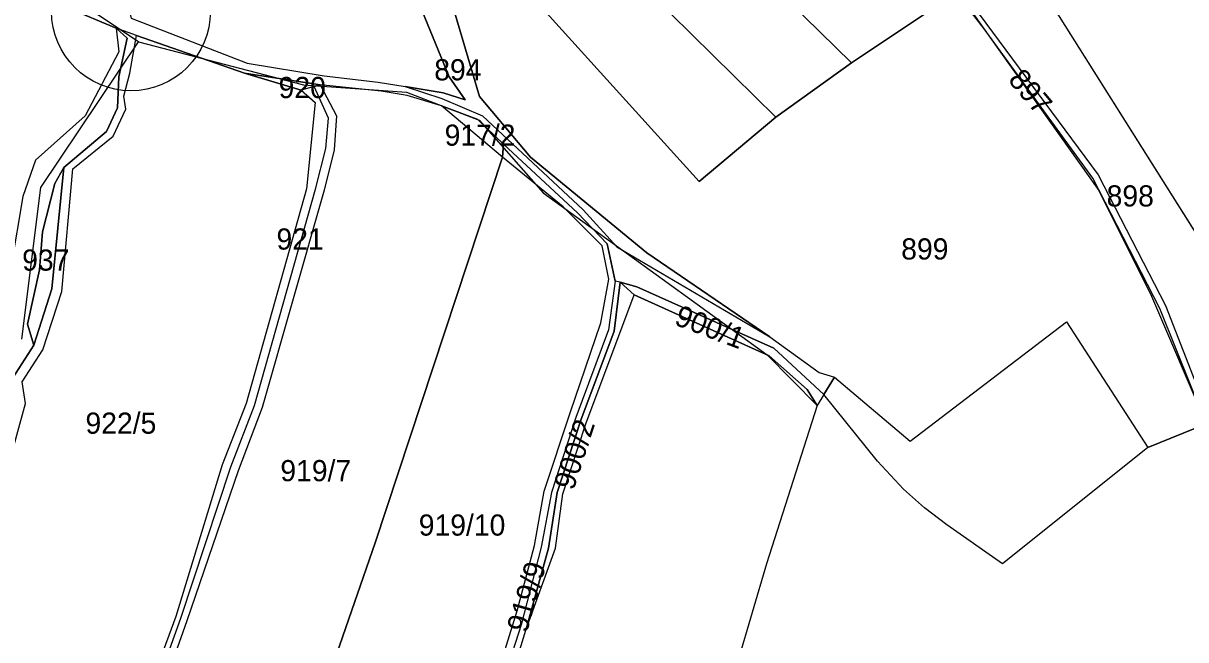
# Model space of a CAD drawing. Extents: x -623250 to -619626, y -1079612 to -1075424.
# Drawn here: x -621038 to -620489, y -1077899 to -1077608 of the extents above; entities that cross this region are included whole.
import ezdxf

# ---------------------------------------------------------------- set-up
doc = ezdxf.new("R2010")
doc.units = 0
for name, color, linetype in [('Bodové pole k revizi', 7, 'Continuous'), ('Cestní síť', 7, 'Continuous'), ('Hranice převzatá (KoPÚ Hrušová)', 7, 'Continuous'), ('Katastrální hranice', 7, 'Continuous'), ('Parcela nároku', 7, 'Continuous'), ('Parcelní číslo', 7, 'Continuous'), ('Vodní toky', 7, 'Continuous')]:
    doc.layers.add(name, color=color, linetype=linetype)

msp = doc.modelspace()

# ---------------------------------------------------------------- linework, layer by layer
at = {"layer": 'Bodové pole k revizi'}
msp.add_circle((-620987.23, -1077602.53), 37.5, dxfattribs=at)
at = {"layer": 'Cestní síť'}
for p, q in [((-620983.73, -1077616.96), (-621006.18, -1077601.9)), ((-621029.87, -1077685.72), (-620983.73, -1077616.96)), ((-620983.73, -1077616.96), (-620905.72, -1077637.25)), ((-620905.72, -1077637.25), (-620857.11, -1077640.69)), ((-620857.11, -1077640.69), (-620822.79, -1077653.85)), ((-620822.79, -1077653.85), (-620792.48, -1077688.19)), ((-621038.71, -1077757.43), (-621029.87, -1077685.72)), ((-620792.48, -1077688.19), (-620736.42, -1077728.82)), ((-620736.42, -1077728.82), (-620686.84, -1077764.76)), ((-620686.84, -1077764.76), (-620663.17, -1077788.68))]:
    msp.add_line(p, q, dxfattribs=at)
at = {"layer": 'Hranice převzatá (KoPÚ Hrušová)'}
msp.add_lwpolyline([(-620479.44, -1077797.32), (-620507, -1077808.5), (-620575.7, -1077863.52), (-620601.95, -1077845.15), (-620612.48, -1077837.08), (-620622.34, -1077828.19), (-620634.73, -1077815.07), (-620659.99, -1077783.48), (-620663.17, -1077788.68), (-620687.13, -1077863.5), (-620700.69, -1077909.5)], dxfattribs=at)
at = {"layer": 'Katastrální hranice'}
for p, q in [((-620453.81, -1077755.63), (-620553.25, -1077597.63)), ((-620619.25, -1077805.5), (-620545.44, -1077749.25)), ((-620545.44, -1077749.25), (-620507, -1077808.5)), ((-620659.99, -1077783.48), (-620654.94, -1077775.38)), ((-620654.94, -1077775.38), (-620619.25, -1077805.5))]:
    msp.add_line(p, q, dxfattribs=at)
at = {"layer": 'Parcela nároku'}
for points in [[(-620611.54, -1077603.19), (-620619.14, -1077595.91), (-620760.97, -1077460.03), (-620813.41, -1077411.33), (-620821.08, -1077412.33), (-620817.96, -1077433.72), (-620827.88, -1077444.11), (-620829.07, -1077450.57), (-620787.71, -1077488.88), (-620646.97, -1077626.81)], [(-620787.71, -1077488.88), (-620829.07, -1077450.57), (-620830.13, -1077456.35), (-620841.72, -1077495.6), (-620762.03, -1077574.2), (-620682.61, -1077652.52), (-620646.97, -1077626.81)], [(-620762.03, -1077574.2), (-620841.72, -1077495.6), (-620850.82, -1077526.41), (-620851.45, -1077542.42), (-620800.08, -1077592.94), (-620718.81, -1077682.81), (-620682.61, -1077652.52)], [(-620852.4, -1077595.58), (-620858.57, -1077544.04), (-620878.3, -1077553.15), (-620975.69, -1077586.93), (-620985.33, -1077593.45), (-620988.73, -1077599.5), (-620987.2, -1077605.73), (-620932.29, -1077627.05), (-620895.94, -1077632.9), (-620870.4, -1077635.97), (-620857.77, -1077638.01), (-620839.72, -1077640.92), (-620829.32, -1077644.28), (-620836.97, -1077633.47)], [(-620844.37, -1077593.81), (-620845.11, -1077577.39), (-620851.45, -1077542.42), (-620858.57, -1077544.04), (-620852.4, -1077595.58), (-620836.97, -1077633.47), (-620829.32, -1077644.28), (-620839.72, -1077640.92), (-620857.77, -1077638.01), (-620840.42, -1077643.71), (-620821.25, -1077651.89), (-620773.73, -1077696.26), (-620757.71, -1077713.72), (-620685.44, -1077756.32), (-620743.55, -1077716.58), (-620798.58, -1077671.35), (-620822.67, -1077642.69), (-620834.66, -1077602.26)], [(-620718.81, -1077682.81), (-620800.08, -1077592.94), (-620851.45, -1077542.42), (-620845.11, -1077577.39), (-620844.37, -1077593.81), (-620834.66, -1077602.26), (-620822.67, -1077642.69), (-620798.58, -1077671.35), (-620743.55, -1077716.58), (-620685.44, -1077756.32), (-620662.26, -1077773.11), (-620654.94, -1077775.38), (-620619.25, -1077805.5), (-620545.44, -1077749.25), (-620507, -1077808.5), (-620479.44, -1077797.32), (-620501.31, -1077742.94), (-620532.98, -1077681.37), (-620584.3, -1077610.83), (-620597.88, -1077593.11), (-620611.54, -1077603.19), (-620646.97, -1077626.81), (-620682.61, -1077652.52)], [(-620530.46, -1077679.74), (-620498.61, -1077741.4), (-620477.3, -1077796.45), (-620479.44, -1077797.32), (-620501.31, -1077742.94), (-620532.98, -1077681.37), (-620584.3, -1077610.83), (-620597.88, -1077593.11), (-620599.32, -1077591.23), (-620596.08, -1077590.97)], [(-620553.25, -1077597.63), (-620557.23, -1077593.02), (-620596.08, -1077590.97), (-620530.46, -1077679.74), (-620498.61, -1077741.4), (-620477.3, -1077796.45), (-620442.63, -1077782.38), (-620453.81, -1077755.63)], [(-621038.22, -1077689.94), (-621054.96, -1077788.21), (-621072.71, -1077845.8), (-621080.5, -1077859.39), (-621082.28, -1077883.4), (-621079.35, -1077909.65), (-621074.64, -1077931.81), (-621064.07, -1077869.81), (-621042.31, -1077789.22), (-621043.08, -1077775.7), (-621033.05, -1077760.18), (-621036.09, -1077750.34), (-621030.49, -1077724.63), (-621029.05, -1077706.73), (-621023.14, -1077683.75), (-621018.93, -1077676.2), (-620998.71, -1077659.22), (-620993.53, -1077648.1), (-620992.91, -1077633.43), (-620988.98, -1077615.13), (-620994.15, -1077610.5), (-620992.91, -1077621.62), (-621008.82, -1077651.88), (-621032.36, -1077672.8)], [(-620933.53, -1077631.69), (-620897.89, -1077637.25), (-620900.76, -1077638.04), (-620906.8, -1077639.72)], [(-620900.27, -1077645.54), (-620904.39, -1077686.35), (-620932.83, -1077787.71), (-620944.23, -1077816.78), (-620966.11, -1077888.43), (-620988.43, -1077949.08), (-620996.39, -1077978.66), (-620985.35, -1077949.77), (-620963.73, -1077889.14), (-620940.04, -1077817.61), (-620928.94, -1077788.67), (-620900.05, -1077686.58), (-620895.24, -1077667.22), (-620893.94, -1077652.95), (-620900.76, -1077638.04), (-620906.8, -1077639.72)], [(-620895.99, -1077686.91), (-620925.3, -1077789.59), (-620936.57, -1077819.5), (-620960.78, -1077890.46), (-620985.69, -1077960.76), (-620920.47, -1077994.08), (-620871.91, -1077853.59), (-620811.81, -1077671.44), (-620840.54, -1077647.21), (-620856.83, -1077642.24), (-620869.03, -1077640.15), (-620897.89, -1077637.25), (-620890.21, -1077651.83), (-620891.22, -1077667.97)], [(-620840.54, -1077647.21), (-620823.33, -1077653.61), (-620811.23, -1077665.26), (-620811.81, -1077671.44)], [(-620826.43, -1077955.22), (-620804.78, -1077885.64), (-620796.72, -1077854.91), (-620792.02, -1077829.18), (-620779.83, -1077792.13), (-620765.35, -1077749.61), (-620761.51, -1077729.06), (-620764.71, -1077713.2), (-620783.04, -1077694.81), (-620811.81, -1077671.44), (-620811.23, -1077665.26), (-620776.36, -1077697.62), (-620762.35, -1077712.35), (-620758.56, -1077729.89), (-620761.69, -1077752.96), (-620777.2, -1077794.38), (-620788.59, -1077829.88), (-620793.56, -1077855.59), (-620802.96, -1077892.36), (-620816.93, -1077935.96)], [(-620783.04, -1077694.81), (-620811.81, -1077671.44), (-620871.91, -1077853.59), (-620920.47, -1077994.08), (-620891.92, -1078009.19), (-620859.73, -1078022.67), (-620905.18, -1078145.77), (-620920.49, -1078194.28), (-620977.45, -1078310.76), (-621000.02, -1078348.69), (-621014.46, -1078377.63), (-621006.54, -1078400.13), (-620940.28, -1078260.6), (-620911.67, -1078198.04), (-620887.7, -1078134.29), (-620848.6, -1078013.01), (-620826.43, -1077955.22), (-620804.78, -1077885.64), (-620796.72, -1077854.91), (-620792.02, -1077829.18), (-620779.83, -1077792.13), (-620765.35, -1077749.61), (-620761.51, -1077729.06), (-620764.71, -1077713.2)], [(-621023.14, -1077683.75), (-621029.05, -1077706.73), (-621030.49, -1077724.63), (-621036.09, -1077750.34), (-621033.05, -1077760.18), (-621024.64, -1077733.63), (-621018.93, -1077676.2)], [(-620756.23, -1077730.51), (-620759.07, -1077753.6), (-620774.81, -1077795.6), (-620785.89, -1077829.76), (-620790.08, -1077856.13), (-620800.77, -1077894.78), (-620786.79, -1077856.13), (-620783.29, -1077830.46), (-620772.41, -1077797.3), (-620749.65, -1077736.41)], [(-620683.64, -1077761.6), (-620659.99, -1077783.48), (-620663.17, -1077788.68), (-620667.83, -1077781.08), (-620685.76, -1077765.18), (-620749.65, -1077736.41), (-620756.23, -1077730.51), (-620748.29, -1077732.63)]]:
    msp.add_lwpolyline(points, close=True, dxfattribs=at)
for points in [[(-621042.92, -1077598.61), (-621016.76, -1077601.01), (-620994.15, -1077610.5), (-620992.91, -1077621.62), (-621008.82, -1077651.88), (-621032.36, -1077672.8), (-621038.22, -1077689.94)], [(-620987.2, -1077605.73), (-620932.29, -1077627.05), (-620895.94, -1077632.9), (-620870.4, -1077635.97), (-620857.77, -1077638.01), (-620840.42, -1077643.71), (-620821.25, -1077651.89), (-620773.73, -1077696.26), (-620757.71, -1077713.72), (-620685.44, -1077756.32), (-620662.26, -1077773.11), (-620654.94, -1077775.38), (-620659.99, -1077783.48), (-620683.64, -1077761.6), (-620748.29, -1077732.63), (-620756.23, -1077730.51), (-620758.56, -1077729.89), (-620762.35, -1077712.35), (-620776.36, -1077697.62), (-620811.23, -1077665.26), (-620823.33, -1077653.61), (-620840.54, -1077647.21), (-620856.83, -1077642.24), (-620869.03, -1077640.15), (-620897.89, -1077637.25), (-620933.53, -1077631.69), (-620984.6, -1077613.84), (-620994.15, -1077610.5), (-621016.76, -1077601.01)], [(-621059.59, -1077869.55), (-621037.01, -1077787.76), (-621038.58, -1077777.48), (-621028.9, -1077762.35), (-621019.92, -1077734.84), (-621014.62, -1077676.88), (-620995.64, -1077661.49), (-620989.68, -1077648.78), (-620990.66, -1077642.5), (-620987.78, -1077631.69), (-620984.6, -1077613.84), (-620994.15, -1077610.5), (-620988.98, -1077615.13), (-620992.91, -1077633.43), (-620993.53, -1077648.1), (-620998.71, -1077659.22), (-621018.93, -1077676.2), (-621024.64, -1077733.63), (-621033.05, -1077760.18), (-621043.08, -1077775.7)], [(-621059.59, -1077869.55), (-621037.01, -1077787.76), (-621038.58, -1077777.48), (-621028.9, -1077762.35), (-621019.92, -1077734.84), (-621014.62, -1077676.88), (-620995.64, -1077661.49), (-620989.68, -1077648.78), (-620990.66, -1077642.5), (-620987.78, -1077631.69), (-620984.6, -1077613.84), (-620933.53, -1077631.69), (-620906.8, -1077639.72), (-620900.27, -1077645.54), (-620904.39, -1077686.35), (-620932.83, -1077787.71), (-620944.23, -1077816.78), (-620966.11, -1077888.43), (-620988.43, -1077949.08), (-620996.39, -1077978.66), (-620996.31, -1077966.5), (-621003.9, -1077958.75), (-621003.37, -1077947.59), (-621057.59, -1077962.86)], [(-621095.78, -1078240.75), (-621053.62, -1078141.34), (-621012.33, -1078024.41), (-621000.18, -1077984.59), (-620996.39, -1077978.66), (-620985.35, -1077949.77), (-620963.73, -1077889.14), (-620940.04, -1077817.61), (-620928.94, -1077788.67), (-620900.05, -1077686.58), (-620895.24, -1077667.22), (-620893.94, -1077652.95), (-620900.76, -1077638.04), (-620897.89, -1077637.25), (-620890.21, -1077651.83), (-620891.22, -1077667.97), (-620895.99, -1077686.91), (-620925.3, -1077789.59), (-620936.57, -1077819.5), (-620960.78, -1077890.46), (-620985.69, -1077960.76), (-620986.94, -1077964.3), (-621049.48, -1078140.79), (-621091.98, -1078240.75)], [(-620936.54, -1078261.78), (-620907.27, -1078197.5), (-620884.02, -1078134.35), (-620844.5, -1078013.8), (-620825.23, -1077961.55), (-620813.43, -1077936.71), (-620800.77, -1077894.78), (-620790.08, -1077856.13), (-620785.89, -1077829.76), (-620774.81, -1077795.6), (-620759.07, -1077753.6), (-620756.23, -1077730.51), (-620758.56, -1077729.89), (-620761.69, -1077752.96), (-620777.2, -1077794.38), (-620788.59, -1077829.88), (-620793.56, -1077855.59), (-620802.96, -1077892.36), (-620816.93, -1077935.96), (-620826.43, -1077955.22), (-620848.6, -1078013.01), (-620887.7, -1078134.29), (-620911.67, -1078198.04), (-620940.28, -1078260.6)], [(-620813.43, -1077936.71), (-620800.77, -1077894.78), (-620786.79, -1077856.13), (-620783.29, -1077830.46), (-620772.41, -1077797.3), (-620749.65, -1077736.41), (-620685.76, -1077765.18), (-620667.83, -1077781.08), (-620663.17, -1077788.68), (-620687.13, -1077863.5), (-620700.69, -1077909.5)]]:
    msp.add_lwpolyline(points, dxfattribs=at)
at = {"layer": 'Vodní toky'}
for p, q in [((-620590.07, -1077602.73), (-620530.12, -1077687.19)), ((-620530.12, -1077687.19), (-620505.28, -1077737.08)), ((-620505.28, -1077737.08), (-620479.44, -1077797.32))]:
    msp.add_line(p, q, dxfattribs=at)

# ---------------------------------------------------------------- texts
at = {"layer": 'Parcelní číslo'}
for s, p in [('894', (-620843.99, -1077635.1)), ('920', (-620917.49, -1077643.48)), ('917/2', (-620839.09, -1077665.98)), ('898', (-620526.44, -1077694.69)), ('921', (-620918.5, -1077715.05)), ('899', (-620623.46, -1077719.73)), ('937', (-621038.6, -1077725)), ('922/5', (-621008.71, -1077802.04)), ('919/7', (-620916.68, -1077824.47)), ('919/10', (-620851.31, -1077850.18))]:
    msp.add_text(s, height=10, dxfattribs=at).set_placement(p)
for s, rotation, p in [('897', 309.9709, (-620573.36, -1077635.03)), ('900/1', 339.2641, (-620731.13, -1077750.33)), ('900/2', 72.06, (-620778.25, -1077829.18)), ('919/9', 74.0347, (-620800.28, -1077896.46))]:
    msp.add_text(s, height=10, rotation=rotation, dxfattribs=at).set_placement(p)

doc.saveas('drawing.dxf')
